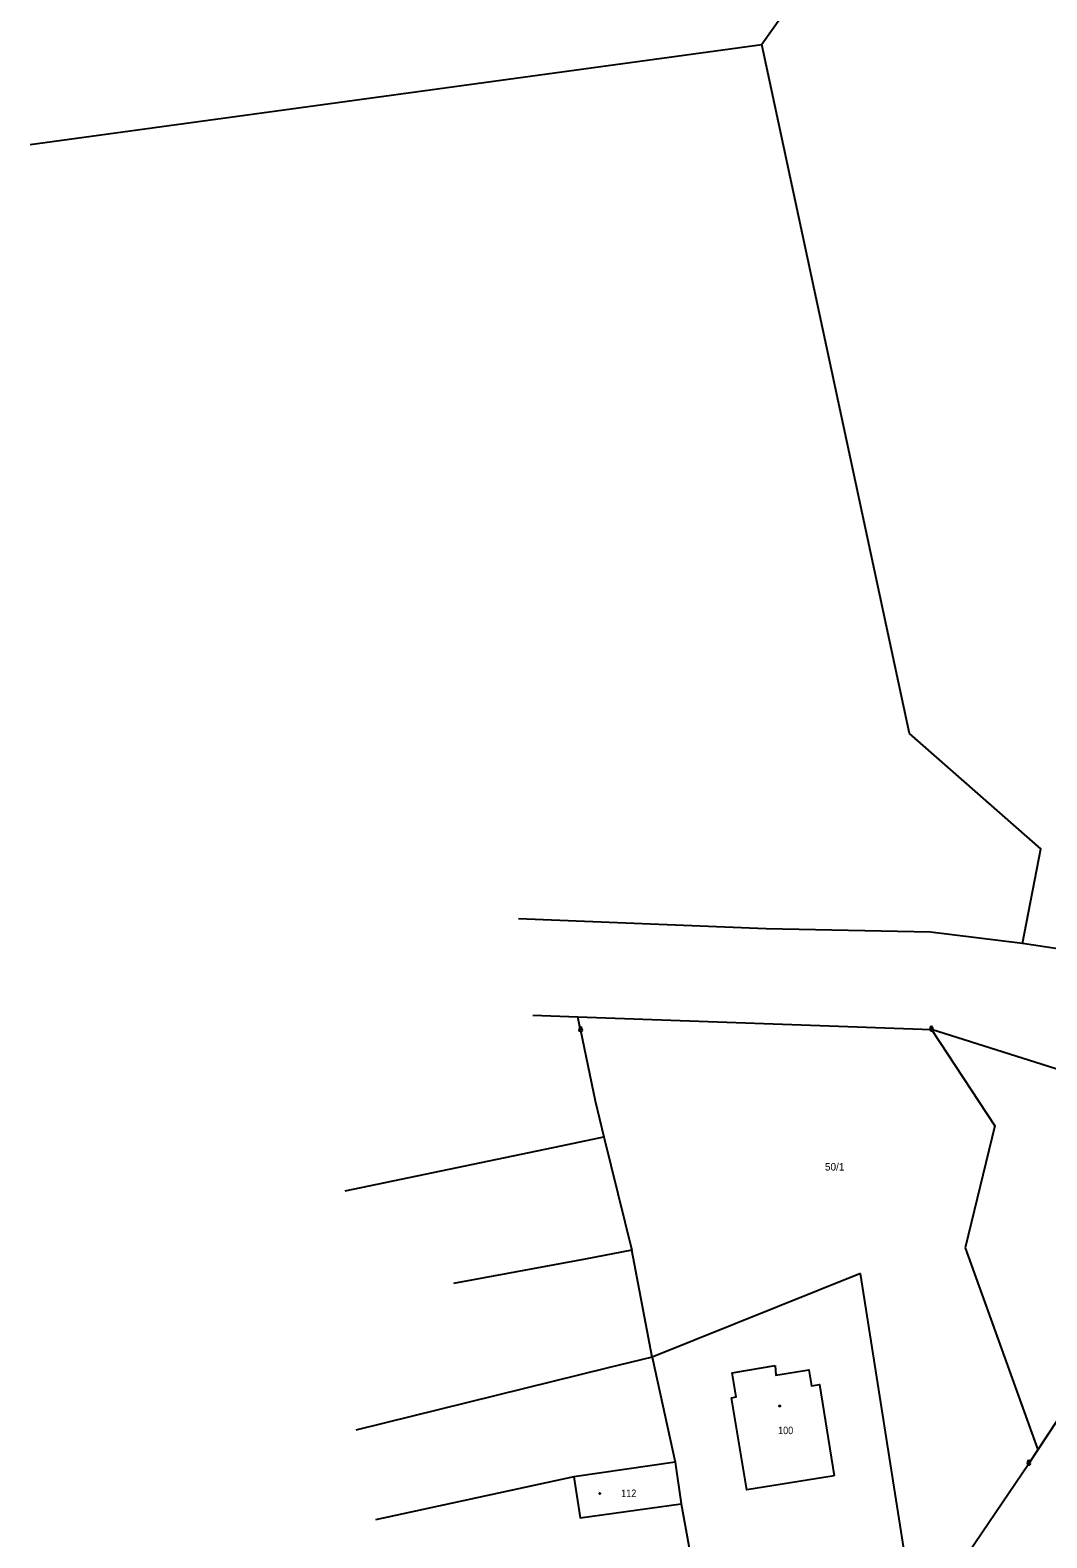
# Model space of a CAD drawing. Extents: x -873052 to -871788, y -1075760 to -1074911.
# Drawn here: x -872995.1 to -872893.4, y -1075410.5 to -1075259.8 of the extents above; entities that cross this region are included whole.
import ezdxf
from ezdxf.enums import TextEntityAlignment as Align

# ---------------------------------------------------------------- set-up
doc = ezdxf.new("R2010")
doc.units = 0
doc.header["$LTSCALE"] = 0.3
for name, color, linetype, lineweight in [('1', 7, 'Continuous', 25), ('24', 7, 'Continuous', 25), ('25', 7, 'Continuous', 25)]:
    doc.layers.add(name, color=color, linetype=linetype, lineweight=lineweight)
doc.layers.add('18', color=7, linetype='Continuous')
doc.layers.add('19', color=7, linetype='Continuous')

msp = doc.modelspace()

# ---------------------------------------------------------------- linework, layer by layer
at = {"layer": '1'}
for p, q in [((-872995.06, -1075271.25), (-872921.93, -1075261.26)), ((-872940.04, -1075359.73), (-872940.31, -1075358.41)), ((-872940.04, -1075359.73), (-872938.59, -1075366.79)), ((-872890, -1075364.39), (-872904.98, -1075359.67)), ((-872901.61, -1075381.47), (-872894.35, -1075401.67)), ((-872932.9, -1075392.4), (-872930.6, -1075402.91)), ((-872924.89, -1075393.97), (-872920.61, -1075393.25)), ((-872930.6, -1075402.91), (-872940.73, -1075404.37)), ((-872930.6, -1075402.91), (-872930, -1075407.05)), ((-872906.47, -1075419.55), (-872895.25, -1075403.04)), ((-872940.73, -1075404.37), (-872960.54, -1075408.66))]:
    msp.add_line(p, q, dxfattribs=at)
for points in [[(-872929.66, -1075079.49), (-872929.31, -1075083.06), (-872907.09, -1075132.44), (-872900.1, -1075151.73), (-872899.26, -1075157.47), (-872903.12, -1075234.73), (-872921.93, -1075261.26)], [(-872873.24, -1075371.8), (-872874.52, -1075366.66), (-872879.17, -1075361.02), (-872864.65, -1075355.86), (-872861.65, -1075354.85), (-872862.66, -1075351.84), (-872865.66, -1075352.85), (-872882.06, -1075357.49), (-872890.82, -1075351.83), (-872895.87, -1075351.06), (-872894.06, -1075341.62), (-872907.18, -1075330.08), (-872921.93, -1075261.26)], [(-872895.87, -1075351.06), (-872905.07, -1075349.94), (-872921.49, -1075349.6), (-872946.26, -1075348.6)], [(-872944.81, -1075358.25), (-872940.31, -1075358.41), (-872904.98, -1075359.67)], [(-872904.98, -1075359.67), (-872898.64, -1075369.3), (-872901.61, -1075381.47)], [(-872938.59, -1075366.79), (-872937.71, -1075370.38), (-872934.92, -1075381.73)], [(-872963.57, -1075375.79), (-872941.99, -1075371.28), (-872937.71, -1075370.38)], [(-872934.92, -1075381.73), (-872939.59, -1075382.6), (-872952.75, -1075385.06)], [(-872912.08, -1075384.05), (-872932.9, -1075392.4), (-872934.92, -1075381.73)], [(-872926.22, -1075427.82), (-872906.47, -1075419.55), (-872912.08, -1075384.05)], [(-872932.9, -1075392.4), (-872937.28, -1075393.48), (-872962.51, -1075399.69)], [(-872924.95, -1075396.46), (-872924.49, -1075396.38), (-872924.89, -1075393.97)], [(-872920.61, -1075393.25), (-872920.53, -1075394.19), (-872917.24, -1075393.67), (-872916.98, -1075395.27), (-872916.16, -1075395.14), (-872914.71, -1075404.28)], [(-872914.71, -1075404.28), (-872923.44, -1075405.65), (-872924.95, -1075396.46)], [(-872891.52, -1075397.38), (-872894.35, -1075401.67), (-872895.25, -1075403.04)], [(-872940.73, -1075404.37), (-872940.07, -1075408.47), (-872930, -1075407.05), (-872926.22, -1075427.82)]]:
    msp.add_lwpolyline(points, dxfattribs=at)
at = {"layer": '24'}
for centre, radius in [((-872940.0395, -1075359.7295), 0.1505), ((-872940.0395, -1075359.7295), 0.00652), ((-872904.9795, -1075359.6695), 0.1505), ((-872904.9795, -1075359.6695), 0.00652), ((-872895.2495, -1075403.0395), 0.1505), ((-872895.2495, -1075403.0395), 0.00652)]:
    msp.add_circle(centre, radius, dxfattribs=at)
for centre in [(-872940.0396, -1075359.5601), (-872904.9796, -1075359.5001), (-872895.2496, -1075402.8701)]:
    msp.add_arc(centre, 0.1311, 328.53402, 210.28963, dxfattribs=at)
at = {"layer": '25'}
for centre in [(-872920.1495, -1075397.2895), (-872938.1295, -1075406.0295)]:
    msp.add_circle(centre, 0.0525, dxfattribs=at)

# ---------------------------------------------------------------- texts
at = {"layer": '18'}
msp.add_text('50/1', height=0.75, dxfattribs=at).set_placement((-872914.6495, -1075373.76), align=Align.CENTER)
at = {"layer": '19', "width": 0.9}
for s, p in [('100', (-872919.5495, -1075400.1)), ('112', (-872935.2295, -1075406.38))]:
    msp.add_text(s, height=0.75, dxfattribs=at).set_placement(p, align=Align.CENTER)

doc.saveas('drawing.dxf')
